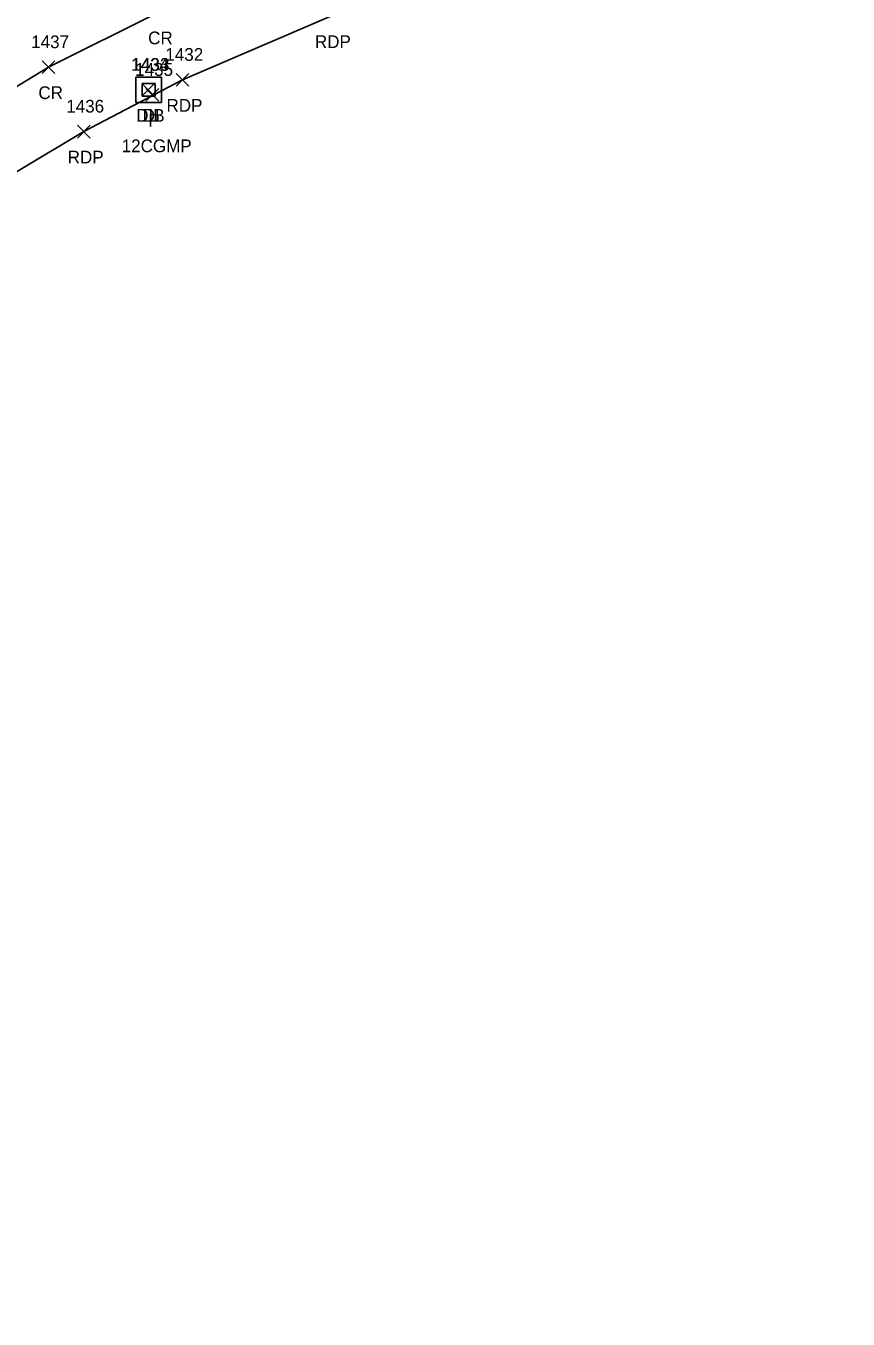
# Model space of a CAD drawing. Extents: x 1688195 to 1692013, y 424605 to 441234.
# Drawn here: x 1691624.9 to 1691754.1, y 438838.2 to 439041.4 of the extents above; entities that cross this region are included whole.
import ezdxf

# ---------------------------------------------------------------- set-up
doc = ezdxf.new("R2010")
doc.units = 0
for name, color, linetype in [('D_A', 7, 'Continuous'), ('D_C', 7, 'Continuous'), ('D_I', 7, 'Continuous'), ('D_TIC', 7, 'Continuous'), ('DS', 7, 'Continuous'), ('P_A', 7, 'Continuous'), ('P_I', 7, 'Continuous'), ('P_TIC', 7, 'Continuous'), ('PET', 7, 'Continuous'), ('PRC', 7, 'Continuous')]:
    doc.layers.add(name, color=color, linetype=linetype)

msp = doc.modelspace()

# ---------------------------------------------------------------- linework, layer by layer
at = {"layer": 'D_TIC'}
for points in [[(1691643.16, 439030.32), (1691645.16, 439032.32)], [(1691645.16, 439030.32), (1691643.16, 439032.32)], [(1691643.8, 439029.53), (1691645.8, 439031.53)], [(1691645.8, 439029.53), (1691643.8, 439031.53)]]:
    msp.add_lwpolyline(points, dxfattribs=at)
at = {"layer": 'DS'}
for p, q in [((1691642.22, 439033.32), (1691646.22, 439033.32)), ((1691642.22, 439029.32), (1691642.22, 439033.32)), ((1691643.22, 439030.32), (1691643.22, 439032.32)), ((1691643.22, 439032.32), (1691645.22, 439032.32)), ((1691645.22, 439032.32), (1691645.22, 439030.32)), ((1691646.22, 439033.32), (1691646.22, 439029.32)), ((1691645.22, 439030.32), (1691643.22, 439030.32)), ((1691644.22, 439031.32), (1691644.22, 439031.32)), ((1691644.22, 439031.32), (1691644.22, 439031.32)), ((1691646.22, 439029.32), (1691642.22, 439029.32))]:
    msp.add_line(p, q, dxfattribs=at)
at = {"layer": 'P_TIC'}
for points in [[(1691627.46, 439033.88), (1691629.46, 439035.88)], [(1691629.46, 439033.88), (1691627.46, 439035.88)], [(1691648.54, 439031.89), (1691650.54, 439033.89)], [(1691650.54, 439031.89), (1691648.54, 439033.89)], [(1691633.02, 439023.76), (1691635.02, 439025.76)], [(1691635.02, 439023.76), (1691633.02, 439025.76)]]:
    msp.add_lwpolyline(points, dxfattribs=at)
at = {"layer": 'PET'}
msp.add_lwpolyline([(1691672.86, 439042.9), (1691649.54, 439032.89), (1691634.02, 439024.76), (1691613.34, 439012.41), (1691591.31, 438997.78), (1691582.05, 438990.56), (1691567.39, 438977.9), (1691551.1, 438962.07), (1691527.82, 438937.62), (1691487.26, 438894.03), (1691457.21, 438860.6), (1691436.01, 438838.17)], dxfattribs=at)
at = {"layer": 'PRC'}
msp.add_lwpolyline([(1691888.13, 439193.66), (1691921.53, 439164.99), (1691933.61, 439155.1), (1691905.33, 439143.8), (1691864.7, 439127.18), (1691822.78, 439112.3), (1691787.26, 439099.58), (1691756.92, 439088.3), (1691729.19, 439077.85), (1691704.03, 439068.3), (1691667.7, 439053.5), (1691645.71, 439043.49), (1691628.46, 439034.88), (1691608.73, 439022.92), (1691585.22, 439006.39), (1691574.92, 438998.75), (1691559.84, 438985.93), (1691543.5, 438970.76), (1691518.61, 438946.02), (1691478.27, 438903.21), (1691447.81, 438870), (1691426.94, 438847.45)], dxfattribs=at)

# ---------------------------------------------------------------- texts
at = {"layer": 'D_A'}
for s, p in [('DIB', (1691642.27, 439026.32)), ('DI', (1691643.28, 439026.32)), ('P', (1691644.17, 439025.53))]:
    msp.add_text(s, height=2, dxfattribs=at).set_placement(p)
at = {"layer": 'D_C'}
msp.add_text('12CGMP', height=2, dxfattribs=at).set_placement((1691639.98, 439021.53))
at = {"layer": 'D_I'}
for s, p in [('1434', (1691641.47, 439034.32)), ('1433', (1691641.53, 439034.32)), ('1435', (1691642.1, 439033.53))]:
    msp.add_text(s, height=2, dxfattribs=at).set_placement(p)
at = {"layer": 'P_A'}
for s, p in [('CR', (1691644.14, 439038.49)), ('RDP', (1691670.34, 439037.9)), ('CR', (1691626.89, 439029.88)), ('RDP', (1691647.02, 439027.89)), ('RDP', (1691631.5, 439019.76))]:
    msp.add_text(s, height=2, dxfattribs=at).set_placement(p)
at = {"layer": 'P_I'}
for s, p in [('1437', (1691625.76, 439037.88)), ('1432', (1691646.84, 439035.89)), ('1436', (1691631.27, 439027.76))]:
    msp.add_text(s, height=2, dxfattribs=at).set_placement(p)

doc.saveas('drawing.dxf')
